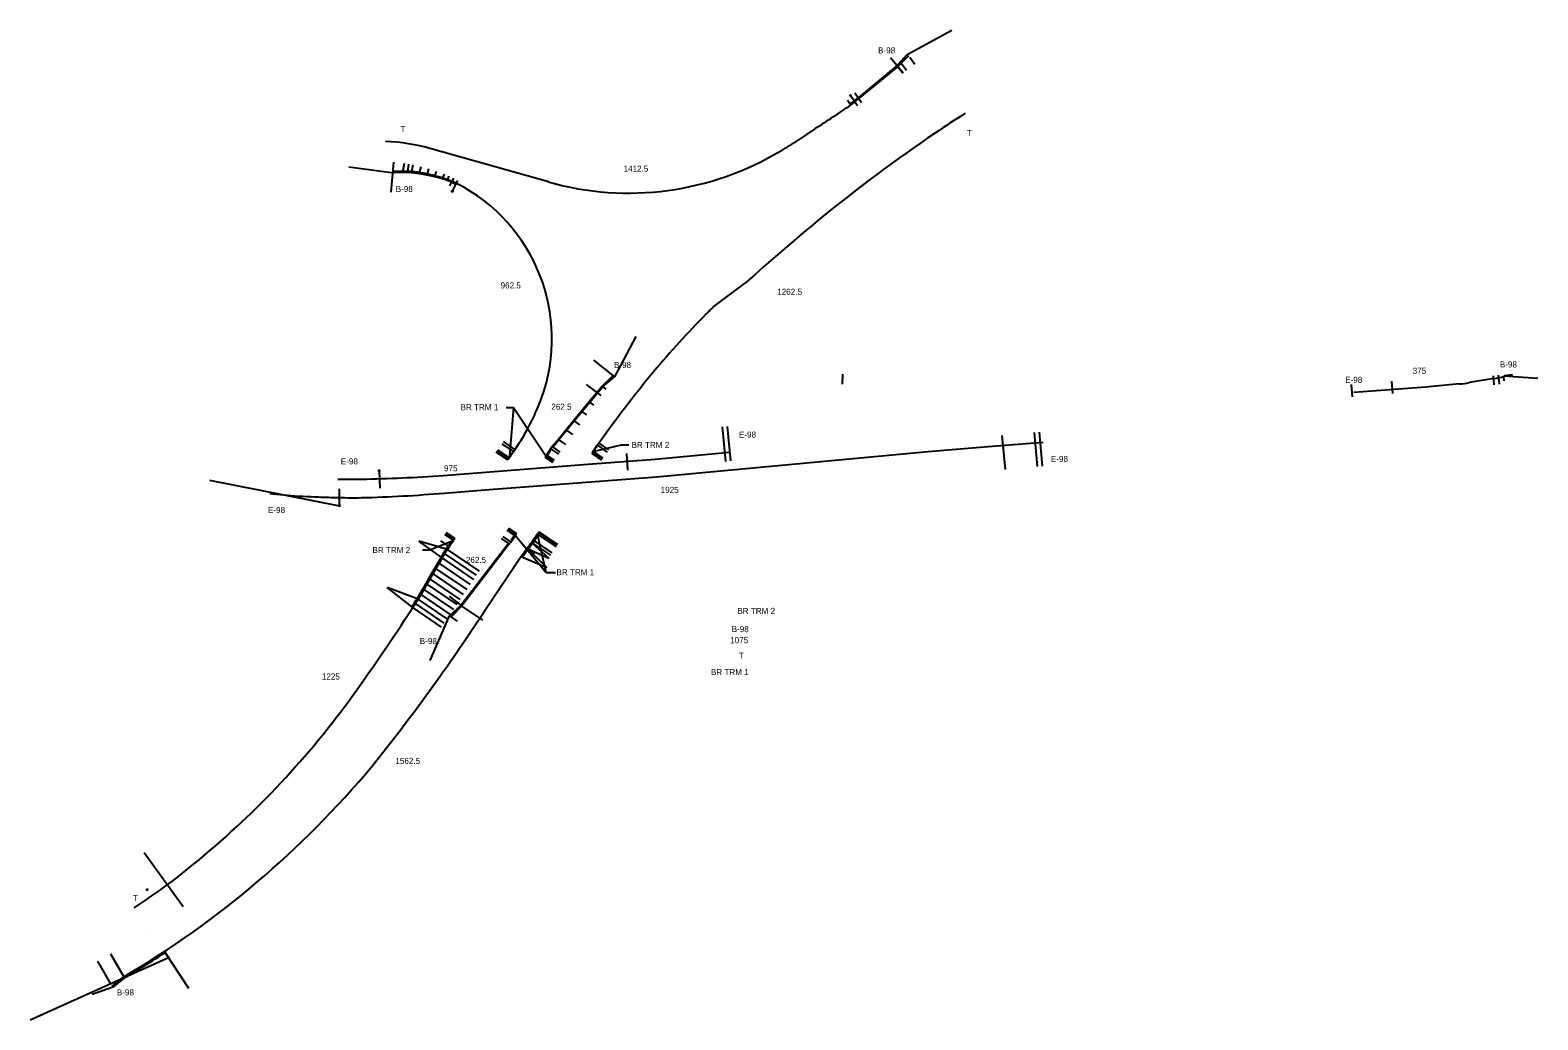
# Model space of a CAD drawing. Extents: x 1394788 to 1443949, y 571575 to 592763.
# Drawn here: x 1440208 to 1443949, y 590308 to 592763 of the extents above; entities that cross this region are included whole.
import ezdxf

# ---------------------------------------------------------------- set-up
doc = ezdxf.new("R2010")
doc.units = 0
for name, color, linetype in [('Level 24', 7, 'Continuous'), ('Level 62', 7, 'Continuous'), ('Level 63', 7, 'Continuous'), ('RD_P_GR_Rt', 7, 'Continuous')]:
    doc.layers.add(name, color=color, linetype=linetype)

msp = doc.modelspace()

# ---------------------------------------------------------------- linework, layer by layer
at = {"layer": 'Level 24'}
for p, q in [((1442387.1, 592699.1), (1442361.1, 592672.4)), ((1442361.1, 592672.4), (1442244.4, 592577.1)), ((1442154.8, 592518.1), (1442113.7, 592489.8)), ((1441493.7, 592386.3), (1441203.3, 592468.6)), ((1441110.5, 592413.9), (1441145.7, 592413)), ((1442167.6, 592294.5), (1442167.6, 592294.5)), ((1441904.1, 592077.4), (1441983, 592135.6)), ((1441884.7, 592058.1), (1441884.7, 592058.1)), ((1441626.8, 591879.6), (1441654.1, 591906.1)), ((1441755.2, 591916), (1441755.2, 591916)), ((1442223.6, 591884.7), (1442224.3, 591909.7)), ((1443839.3, 591898.9), (1443779, 591888.5)), ((1441595.3, 591841.8), (1441626.8, 591879.6)), ((1443670.6, 591877.4), (1443491.9, 591863.8)), ((1443754.2, 591885.2), (1443670.6, 591877.4)), ((1441476.9, 591849.9), (1441476.9, 591849.8)), ((1441556.6, 591795.4), (1441575.9, 591818.7)), ((1441575.9, 591818.7), (1441595.3, 591841.8)), ((1441537.5, 591772.1), (1441556.6, 591795.4)), ((1441411, 591722.7), (1441422.5, 591739.7)), ((1441422.5, 591739.7), (1441422.5, 591739.7)), ((1441503.5, 591729.9), (1441518.5, 591748.6)), ((1441518.5, 591748.6), (1441537.5, 591772.1)), ((1441615.2, 591733.7), (1441629.5, 591752.9)), ((1441411, 591722.7), (1441393.4, 591696.9)), ((1441503.5, 591729.9), (1441486, 591704)), ((1441615.2, 591733.7), (1441601.2, 591713)), ((1441455.7, 591497.6), (1441469.7, 591518.3)), ((1441247.9, 591481.5), (1441243.4, 591474.9)), ((1441261.9, 591502.3), (1441247.9, 591481.5)), ((1441396.5, 591488.4), (1441278.7, 591335.3)), ((1441396.5, 591488.4), (1441400.4, 591493.3)), ((1441400.4, 591493.3), (1441414.4, 591514)), ((1441452.2, 591492.4), (1441455.7, 591497.6)), ((1441230, 591453.7), (1441199.8, 591401.8)), ((1441426.5, 591457), (1441332.6, 591318)), ((1441184.6, 591375.9), (1441170.5, 591351.7)), ((1441199.8, 591401.8), (1441184.6, 591375.9)), ((1441278.7, 591335.3), (1441252.5, 591307.7)), ((1441332.6, 591318), (1441332.6, 591318)), ((1441055.5, 590936.6), (1441055.4, 590936.5)), ((1440544.8, 590640.4), (1440544.8, 590640.4)), ((1440411.9, 590391.6), (1440440.5, 590415.1))]:
    msp.add_line(p, q, dxfattribs=at)
for points in [[(1441396.4, 591701.4), (1441395.1, 591702.3), (1441396.1, 591703.7), (1441397.3, 591702.8)], [(1441398.2, 591704), (1441396.9, 591704.9), (1441397.8, 591706.2), (1441399.1, 591705.4)], [(1441399.9, 591706.6), (1441398.6, 591707.4), (1441399.6, 591708.8), (1441400.9, 591707.9)], [(1441401.7, 591709.1), (1441400.4, 591710), (1441401.4, 591711.4), (1441402.6, 591710.5)], [(1441403.5, 591711.7), (1441402.2, 591712.6), (1441403.1, 591714), (1441404.4, 591713.1)], [(1441407, 591716.9), (1441405.7, 591717.8), (1441406.6, 591719.2), (1441407.9, 591718.3)], [(1441410.5, 591722.1), (1441409.2, 591723), (1441410.1, 591724.3), (1441411.4, 591723.5)], [(1441490.3, 591707.6), (1441489, 591708.5), (1441489.9, 591709.9), (1441491.2, 591709)], [(1441492, 591710.2), (1441490.8, 591711.1), (1441491.7, 591712.5), (1441493, 591711.6)], [(1441493.8, 591712.8), (1441492.5, 591713.7), (1441493.5, 591715.1), (1441494.7, 591714.2)], [(1441495.6, 591715.4), (1441494.3, 591716.3), (1441495.2, 591717.6), (1441496.5, 591716.8)], [(1441497.3, 591718), (1441496, 591718.9), (1441497, 591720.2), (1441498.3, 591719.4)], [(1441500.8, 591723.2), (1441499.5, 591724), (1441500.5, 591725.4), (1441501.7, 591724.5)], [(1441504.3, 591728.4), (1441503, 591729.2), (1441503.9, 591730.6), (1441505.2, 591729.7)], [(1441605.5, 591716.6), (1441604.2, 591717.4), (1441605.2, 591718.8), (1441606.5, 591718)], [(1441609.1, 591721.7), (1441607.8, 591722.6), (1441608.7, 591724), (1441610, 591723.1)], [(1441612.6, 591726.9), (1441611.3, 591727.8), (1441612.2, 591729.2), (1441613.5, 591728.3)], [(1441616, 591732.1), (1441614.7, 591733), (1441615.7, 591734.4), (1441617, 591733.5)], [(1441247.4, 591481), (1441246.1, 591481.9), (1441247, 591483.2), (1441248.3, 591482.4)], [(1441250.9, 591486.2), (1441249.6, 591487), (1441250.5, 591488.4), (1441251.8, 591487.5)], [(1441254.4, 591491.3), (1441253.1, 591492.2), (1441254, 591493.6), (1441255.3, 591492.7)], [(1441257.9, 591496.5), (1441256.6, 591497.4), (1441257.5, 591498.8), (1441258.8, 591497.9)], [(1441395.7, 591489.9), (1441397, 591489.1), (1441396.1, 591487.7), (1441394.8, 591488.5)], [(1441399.5, 591494.9), (1441400.8, 591494), (1441399.9, 591492.6), (1441398.6, 591493.5)], [(1441403, 591500.1), (1441404.3, 591499.2), (1441403.4, 591497.8), (1441402.1, 591498.7)], [(1441404.8, 591502.7), (1441406.1, 591501.8), (1441405.1, 591500.4), (1441403.8, 591501.3)], [(1441406.5, 591505.3), (1441407.8, 591504.4), (1441406.9, 591503), (1441405.6, 591503.9)], [(1441408.3, 591507.8), (1441409.6, 591507), (1441408.6, 591505.6), (1441407.3, 591506.5)], [(1441410, 591510.4), (1441411.3, 591509.6), (1441410.4, 591508.2), (1441409.1, 591509)], [(1441452.7, 591493.1), (1441454, 591492.2), (1441453.1, 591490.8), (1441451.8, 591491.7)], [(1441456.2, 591498.3), (1441457.5, 591497.4), (1441456.5, 591496), (1441455.2, 591496.9)], [(1441459.7, 591503.4), (1441461, 591502.6), (1441460, 591501.2), (1441458.7, 591502.1)], [(1441461.4, 591506), (1441462.7, 591505.2), (1441461.8, 591503.8), (1441460.5, 591504.6)], [(1441463.2, 591508.6), (1441464.5, 591507.7), (1441463.5, 591506.4), (1441462.2, 591507.2)], [(1441464.9, 591511.2), (1441466.2, 591510.3), (1441465.3, 591508.9), (1441464, 591509.8)], [(1441466.7, 591513.8), (1441468, 591512.9), (1441467, 591511.5), (1441465.8, 591512.4)]]:
    msp.add_lwpolyline(points, close=True, dxfattribs=at)
for centre, radius, start, end in [((1440103.9, 595728.6), 3809.7, 302.5726, 304.1841), ((1444594.8, 589334.9), 3827.6, 122.682, 124.0075), ((1440103.9, 595728.6), 3811.7, 301.0598, 301.8226), ((1444582.6, 589350.6), 3807.7, 123.9879, 129.3634), ((1441070.4, 591996.7), 490.3, 74.2782, 87.7855), ((1441693.1, 593089.9), 731.3, 254.1723, 301.0598), ((1441112.6, 592029.6), 384.9, 66.572, 85.0583), ((1441069.9, 591996.8), 432.7, 340.1455, 63.106), ((1445310.9, 588456.9), 4960.6, 129.3199, 132.1333), ((1443463.8, 590489.4), 2225.8, 135.1873, 140.1404), ((1443964.2, 590083.6), 2870, 140.3241, 144.4345), ((1443725.4, 592559.7), 670.6, 279.7767, 281.9658), ((1443719.5, 592242.2), 358.7, 275.5369, 279.5343), ((1440889.1, 592071.6), 628.2, 328.1043, 339.3285), ((1440987.2, 594785.4), 3136.4, 270.7733, 274.4908), ((1440956.1, 594788.3), 3185.8, 271.3303, 275.0412), ((1441775.3, 591222.2), 420.4, 142.6446, 146.0535), ((1441136.1, 591713.3), 385.7, 322.2617, 325.0498), ((1441570.5, 591254), 394.8, 145.9702, 149.6012), ((1435901.7, 594761.8), 6276.5, 324.28195, 326.86005), ((1440765.6, 591589.2), 469.4, 326.5467, 329.6009), ((1437313.1, 593946.7), 4802.7, 321.1896, 326.8154), ((1439210.3, 592415.3), 2220.6, 321.3653, 323.6036), ((1439210.3, 592415.3), 2220.6, 306.9394, 321.3653), ((1439245.5, 592447.7), 2357.8, 300.4521, 320.1404), ((1439245.5, 592447.7), 2225.8, 303.258, 305.7135)]:
    msp.add_arc(centre, radius, start, end, dxfattribs=at)
msp.add_spline([(1441884.7, 592058.1), (1441889, 592062.5), (1441893.4, 592066.8), (1441897.7, 592071.1), (1441902, 592075.4), (1441904.1, 592077.4)], degree=3, dxfattribs=at)
at = {"layer": 'Level 62'}
for p, q in [((1442342.8, 592694.5), (1442374.1, 592656.8)), ((1442370, 592679.7), (1442382.4, 592663)), ((1442390.8, 592695.3), (1442403.3, 592678.5)), ((1442361.1, 592672.4), (1442373.2, 592656.1)), ((1442382.4, 592663), (1442382.4, 592663)), ((1442243.9, 592600), (1442260.3, 592575.9)), ((1442254.2, 592607), (1442270.7, 592582.9)), ((1442236.2, 592589.1), (1442244.4, 592577.1)), ((1442260.3, 592575.9), (1442260.3, 592575.9)), ((1441105.4, 592477.7), (1441105.4, 592477.7)), ((1441103.7, 592360.8), (1441110.6, 592435.6)), ((1441110.6, 592435.6), (1441110.6, 592435.6)), ((1441133.7, 592414.7), (1441136.4, 592432.5)), ((1441136.4, 592432.5), (1441136.4, 592432.5)), ((1441144.7, 592413.2), (1441147.8, 592430.6)), ((1441147.8, 592430.6), (1441147.8, 592430.6)), ((1441155.2, 592411.8), (1441158.6, 592428.5)), ((1441158.6, 592428.5), (1441158.6, 592428.5)), ((1441168.4, 592426.4), (1441168.4, 592426.4)), ((1441174.3, 592409.2), (1441178.1, 592424)), ((1441178.1, 592424), (1441178.1, 592424)), ((1441187.8, 592421.5), (1441187.8, 592421.5)), ((1441193.5, 592406), (1441197.4, 592418.7)), ((1441197.4, 592418.7), (1441197.4, 592418.7)), ((1441206.9, 592415.7), (1441206.9, 592415.7)), ((1441212.6, 592401.8), (1441216.4, 592412.5)), ((1441216.4, 592412.5), (1441216.4, 592412.5)), ((1441225.8, 592409), (1441225.8, 592409)), ((1441235.1, 592405.6), (1441230.5, 592395)), ((1441246.6, 592400.6), (1441242.6, 592391.4)), ((1441246.6, 592400.6), (1441246.6, 592400.6)), ((1441249.6, 592376.9), (1441254.8, 592388)), ((1441258, 592395.5), (1441254.8, 592388)), ((1441255.6, 592363.1), (1441269.2, 592389.9)), ((1441605.8, 591944.1), (1441658, 591903)), ((1441659.1, 591902.2), (1441659.1, 591902.2)), ((1443588.8, 591861.2), (1443586.4, 591891.9)), ((1443840.7, 591883.3), (1443838.6, 591905.8)), ((1443853.2, 591884.4), (1443851, 591907)), ((1443885.4, 591907.7), (1443864.2, 591905.7)), ((1443864.3, 591905.7), (1443948.7, 591899.6)), ((1443885.6, 591905.7), (1443864.4, 591903.7)), ((1443865.4, 591892.6), (1443864.4, 591903.7)), ((1441587.8, 591883.9), (1441624, 591856.6)), ((1441624, 591856.6), (1441624, 591856.6)), ((1441626.9, 591879.6), (1441636.1, 591872.5)), ((1441636.1, 591872.5), (1441636.1, 591872.5)), ((1443489, 591853.5), (1443486.7, 591884.3)), ((1441388.9, 591826.9), (1441407.1, 591826.9)), ((1441407.1, 591826.9), (1441397.5, 591706.7)), ((1441407.1, 591826.9), (1441487.8, 591706.7)), ((1441575.3, 591817.8), (1441588.2, 591808.4)), ((1441594.8, 591840.9), (1441606, 591832.6)), ((1441597.1, 591820.5), (1441597.1, 591820.5)), ((1441606, 591832.6), (1441606, 591832.6)), ((1441615, 591844.6), (1441615, 591844.6)), ((1441556, 591794.6), (1441570.7, 591784.1)), ((1441570.7, 591784.1), (1441570.7, 591784.1)), ((1441579.4, 591796.3), (1441579.4, 591796.3)), ((1441588.2, 591808.4), (1441588.2, 591808.4)), ((1441924.9, 591778.8), (1441932.9, 591693.1)), ((1441937.3, 591780), (1441945.3, 591694.3)), ((1441410.9, 591722.8), (1441382.2, 591742.3)), ((1441518, 591747.7), (1441536, 591735.1)), ((1441536.9, 591771.2), (1441553.2, 591759.7)), ((1441544.6, 591747.4), (1441544.6, 591747.4)), ((1441553.2, 591759.7), (1441553.2, 591759.7)), ((1441561.9, 591771.9), (1441561.9, 591771.9)), ((1442627.8, 591672.8), (1442619.9, 591757.3)), ((1442707.4, 591680.3), (1442699.6, 591764.7)), ((1442719.9, 591681.4), (1442712, 591765.9)), ((1441393.4, 591696.9), (1441364.6, 591716.5)), ((1441394.6, 591698.7), (1441365.8, 591718.2)), ((1441396.9, 591702.1), (1441368.1, 591721.6)), ((1441407.4, 591717.6), (1441378.7, 591737.1)), ((1441505.2, 591690.8), (1441486, 591704)), ((1441506.4, 591692.5), (1441487.2, 591705.8)), ((1441508.7, 591695.9), (1441489.5, 591709.2)), ((1441519.4, 591711.4), (1441500.1, 591724.6)), ((1441522.9, 591716.5), (1441503.7, 591729.8)), ((1441527.4, 591722.8), (1441527.4, 591722.8)), ((1441536, 591735.1), (1441536, 591735.1)), ((1441601.2, 591713), (1441625.2, 591696)), ((1441602.4, 591714.6), (1441626.3, 591697.7)), ((1441674.2, 591733.6), (1441604.2, 591717.3)), ((1441604.8, 591718.1), (1441628.8, 591701.1)), ((1441615.6, 591733.4), (1441639.6, 591716.5)), ((1441619.2, 591738.5), (1441643.2, 591721.6)), ((1441693.4, 591733.6), (1441674.2, 591733.6)), ((1441691.2, 591671.7), (1441688.1, 591712.6)), ((1441073.8, 591670), (1441075.5, 591626.5)), ((1440652.7, 591646.3), (1440975.5, 591583.4)), ((1440975.5, 591625.4), (1440975.5, 591625.4)), ((1440975.5, 591583.4), (1440975.5, 591625.4)), ((1441075.5, 591626.5), (1441075.5, 591626.5)), ((1441238.7, 591515.5), (1441260.7, 591500.6)), ((1441239.8, 591517.2), (1441261.9, 591502.3)), ((1441391, 591522.3), (1441410.9, 591508.9)), ((1441393.3, 591525.7), (1441413.2, 591512.3)), ((1441394.5, 591527.5), (1441414.4, 591514)), ((1441468.5, 591516.5), (1441515, 591485.1)), ((1441469.7, 591518.3), (1441516.2, 591486.9)), ((1441243.4, 591474.9), (1441172.1, 591495.8)), ((1441230, 591453.7), (1441172.1, 591495.8)), ((1441200, 591473.9), (1441258.9, 591497.9)), ((1441225.8, 591496.5), (1441247.9, 591481.5)), ((1441236.3, 591512), (1441258.4, 591497.1)), ((1441377, 591501.6), (1441396.9, 591488.1)), ((1441380.5, 591506.8), (1441400.4, 591493.3)), ((1441488.6, 591417.1), (1441411.4, 591509.7)), ((1441441.1, 591477.3), (1441490.2, 591429.9)), ((1441441.1, 591477.3), (1441494.8, 591453.2)), ((1441441.6, 591478.1), (1441460.1, 591465.6)), ((1441459.3, 591464.4), (1441441.6, 591478.1)), ((1441452.2, 591492.4), (1441494.8, 591453.2)), ((1441452.2, 591492.4), (1441498.7, 591461)), ((1441455.7, 591497.6), (1441502.2, 591466.2)), ((1441466.2, 591513.1), (1441512.7, 591481.7)), ((1441488.6, 591417.1), (1441466.8, 591513.9)), ((1441181.1, 591473.9), (1441200, 591473.9)), ((1441300.3, 591388.1), (1441222.5, 591440.7)), ((1441308.7, 591400.6), (1441230, 591453.7)), ((1441315.7, 591410.9), (1441236.4, 591464.5)), ((1441322.7, 591421.3), (1441243.4, 591474.9)), ((1441426.5, 591457), (1441490.2, 591429.9)), ((1441283.5, 591363.3), (1441207.3, 591414.8)), ((1441291.9, 591375.7), (1441214.9, 591427.8)), ((1441511.1, 591417.1), (1441488.6, 591417.1)), ((1441170.5, 591351.7), (1441093.5, 591380.8)), ((1441157.3, 591330.5), (1441093.5, 591380.8)), ((1441184.6, 591375.9), (1441258.3, 591326)), ((1441192.2, 591388.8), (1441266.7, 591338.4)), ((1441275.1, 591350.9), (1441199.8, 591401.8)), ((1441228.5, 591282.1), (1441157.3, 591330.5)), ((1441235.6, 591292.4), (1441164.1, 591340.9)), ((1441242.6, 591302.7), (1441170.5, 591351.7)), ((1441177.1, 591362.9), (1441249.9, 591313.6)), ((1441247.5, 591359.3), (1441278.6, 591335.3)), ((1441266.7, 591338.4), (1441266.7, 591338.4)), ((1441269, 591341.8), (1441269, 591341.8)), ((1441331.4, 591299.7), (1441278.6, 591335.3)), ((1441241.5, 591301.2), (1441241.5, 591301.2)), ((1441248, 591310.8), (1441248, 591310.8)), ((1441267.9, 591297.3), (1441248, 591310.8)), ((1441249.9, 591313.6), (1441249.9, 591313.6)), ((1441258.3, 591326), (1441258.3, 591326)), ((1441224.6, 591276.4), (1441224.6, 591276.4)), ((1441233.1, 591288.8), (1441233.1, 591288.8)), ((1440997.6, 591097.5), (1440997.7, 591097.6)), ((1440490.9, 590723.4), (1440587.4, 590589.8)), ((1440587.4, 590589.8), (1440587.4, 590589.8)), ((1440505.1, 590533), (1440505.1, 590533)), ((1440407.5, 590472.2), (1440440.5, 590415.1)), ((1440601.7, 590386.2), (1440541.3, 590477.8)), ((1440208, 590308.4), (1440551.2, 590462.8)), ((1440375.1, 590453.5), (1440408.1, 590396.4))]:
    msp.add_line(p, q, dxfattribs=at)
for centre in [(1442243.4, 592600.6), (1441255.6, 592363.1), (1441073.8, 591670), (1440975.5, 591583.4), (1440498.2, 590631), (1440551.2, 590462.8)]:
    msp.add_circle(centre, 1.5, dxfattribs=at)
at = {"layer": 'Level 63'}
for p, q in [((1442383.6, 592702.6), (1442494.8, 592762.6)), ((1442359.2, 592674.7), (1442262.4, 592594.5)), ((1442359.2, 592674.7), (1442383.6, 592702.6)), ((1442359.2, 592674.7), (1442359.2, 592674.7)), ((1442262.4, 592594.5), (1442262.4, 592594.5)), ((1440998.3, 592423.6), (1441110.5, 592408.9)), ((1440998.3, 592423.6), (1440998.3, 592423.6)), ((1441145.7, 592410), (1441110.5, 592408.9)), ((1441230.6, 592393.9), (1441230.7, 592393.9)), ((1441253.5, 592385.3), (1441253.5, 592385.3)), ((1441710.7, 592002.6), (1441658, 591903)), ((1441627.8, 591877.8), (1441658, 591903)), ((1441596.8, 591840.5), (1441627.8, 591877.8)), ((1441627.3, 591876.9), (1441627.3, 591876.9)), ((1441558.1, 591794.2), (1441577.4, 591817.4)), ((1441577.4, 591817.4), (1441596.8, 591840.5)), ((1441577.4, 591817.4), (1441577.4, 591817.4)), ((1441596.8, 591840.5), (1441596.8, 591840.5)), ((1441539, 591770.8), (1441558.1, 591794.2)), ((1441558.1, 591794.2), (1441558.1, 591794.2)), ((1441505, 591728.7), (1441520.1, 591747.3)), ((1441519.5, 591746.5), (1441519.5, 591746.5)), ((1441520.1, 591747.3), (1441539, 591770.8)), ((1441539, 591770.8), (1441539, 591770.8)), ((1441455.3, 591491.5), (1441472.8, 591517.4)), ((1441245.9, 591484.1), (1441240.9, 591476.6)), ((1441245.9, 591484.1), (1441259.9, 591504.8)), ((1441395, 591489.6), (1441277.1, 591336.6)), ((1441227.4, 591455.2), (1441197.2, 591403.3)), ((1441227.4, 591455.3), (1441227.4, 591455.2)), ((1441240.9, 591476.6), (1441240.9, 591476.6)), ((1441444, 591476.3), (1441444, 591476.3)), ((1441197.2, 591403.3), (1441182, 591377.4)), ((1441197.2, 591403.3), (1441197.2, 591403.3)), ((1441182, 591377.4), (1441167.9, 591353.2)), ((1441182, 591377.4), (1441182, 591377.4)), ((1441167.9, 591353.2), (1441168, 591353.2)), ((1441248.4, 591310.6), (1441277.1, 591336.6)), ((1441277.1, 591336.6), (1441277.1, 591336.6)), ((1441200.6, 591199.1), (1441248.4, 591310.6)), ((1440442.9, 590413), (1440413.4, 590389.1)), ((1440442.4, 590413.9), (1440442.4, 590413.9)), ((1440413.4, 590389.1), (1440361.6, 590370.8)), ((1440361.6, 590370.8), (1440361.6, 590370.8))]:
    msp.add_line(p, q, dxfattribs=at)
msp.add_lwpolyline([(1441230.7, 592393.9), (1441211.9, 592398.9), (1441192.9, 592403), (1441173.9, 592406.2), (1441145.7, 592410)], dxfattribs=at)
for centre, radius, start, end in [((1442077.2, 592819.9), 291.7, 304.5502, 309.4127), ((1441195.4, 592265.8), 132.9, 64.0616, 74.6161), ((1441069.9, 591996.8), 429.7, 63.1089, 64.6959), ((1441136.6, 591714.2), 388.7, 322.2617, 325.0498), ((1441570.5, 591254), 397.8, 145.9702, 149.6012), ((1441775.8, 591223), 417.4, 142.6446, 145.9739), ((1440765.6, 591589.2), 466.4, 326.5778, 329.6009), ((1441135.1, 591446.3), 179.5, 321.9728, 322.3073), ((1439245.5, 592447.7), 2360.8, 300.4764, 303.3379)]:
    msp.add_arc(centre, radius, start, end, dxfattribs=at)
at = {"layer": 'RD_P_GR_Rt'}
for p, q in [((1442584.8, 591730), (1442721.4, 591741.1)), ((1441758.7, 591699), (1441943.3, 591716.2)), ((1441762.4, 591655.1), (1442435.7, 591718)), ((1442435.7, 591718), (1442584.8, 591730)), ((1441232.7, 591658.6), (1441370.4, 591669.2)), ((1441370.4, 591669.2), (1441580.8, 591685.3)), ((1441580.8, 591685.3), (1441758.7, 591699)), ((1441346.6, 591623.2), (1441555.5, 591639.2)), ((1441555.5, 591639.2), (1441762.4, 591655.1)), ((1440802.6, 591613.3), (1440844.5, 591609.4)), ((1441236.1, 591614.8), (1441346.6, 591623.2))]:
    msp.add_line(p, q, dxfattribs=at)
for centre, radius, start, end in [((1441006.9, 593268.1), 1619, 268.7308, 270.7989), ((1440969.9, 593342.6), 1737.8, 265.8877, 268.5053), ((1441006.8, 593255.8), 1652.7, 267.1506, 268.4646), ((1441007.1, 593278.2), 1675, 268.4748, 270.7864)]:
    msp.add_arc(centre, radius, start, end, dxfattribs=at)

# ---------------------------------------------------------------- texts
at = {"layer": 'Level 62'}
for s, p in [('B-98', (1442311.8, 592704.9)), ('T', (1441127.1, 592509.8)), ('T', (1442532.1, 592500.3)), ('1412.5', (1441680.3, 592411.6)), ('B-98', (1441115, 592361.3)), ('962.5', (1441375.2, 592122.1)), ('1262.5', (1442061.6, 592106.5)), ('B-98', (1441656.6, 591924.9)), ('B-98', (1443854.4, 591926.2)), ('E-98', (1443470.7, 591888)), ('375', (1443638.2, 591910.4)), ('BR TRM 1', (1441275.9, 591820.2)), ('262.5', (1441501.1, 591821.1)), ('BR TRM 2', (1441700.1, 591726.6)), ('E-98', (1441966.6, 591752.1)), ('E-98', (1442740.6, 591691.8)), ('E-98', (1440978.8, 591685.8)), ('975', (1441234.9, 591668.6)), ('1925', (1441772.4, 591615.1)), ('E-98', (1440798.1, 591565.2)), ('BR TRM 2', (1441057.3, 591466)), ('262.5', (1441289, 591441.4)), ('BR TRM 1', (1441513.9, 591410.9)), ('BR TRM 2', (1441962.6, 591315)), ('B-98', (1441174.7, 591240.1)), ('1075', (1441944.9, 591242.4)), ('B-98', (1441948.6, 591269.8)), ('T', (1441966.3, 591204.1)), ('BR TRM 1', (1441897.1, 591163.4)), ('1225', (1440931.8, 591152.3)), ('1562.5', (1441114.2, 590943)), ('T', (1440463, 590602.8)), ('B-98', (1440423.1, 590369))]:
    msp.add_text(s, height=15, dxfattribs=at).set_placement(p)

doc.saveas('drawing.dxf')
